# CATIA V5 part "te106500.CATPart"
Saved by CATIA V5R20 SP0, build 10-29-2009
Part number: 1
Definition: NONE
Nomenclature: 1
Source: Unknown
Description: PART-1-DESC
Bounding box of the stored display mesh (mm): x 0 to 500, y -5 to 5, z -5 to 5
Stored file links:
  C:\Users\Utente\Desktop\IO LAVORO\3D X SITO CF\CUMSA\3D files TE\te106500.CATPart
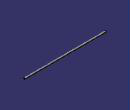
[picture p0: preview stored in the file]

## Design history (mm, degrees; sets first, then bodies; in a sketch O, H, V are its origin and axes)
Body1 "1" (main body)
  Solid1: solid without history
